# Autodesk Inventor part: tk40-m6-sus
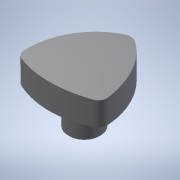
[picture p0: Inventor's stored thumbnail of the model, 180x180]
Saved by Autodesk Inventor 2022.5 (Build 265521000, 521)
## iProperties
Created: 2016-12
Part Number: tk40-m6-sus
Material: 一般
Document SubType Name: Modeling
Designer: imaocorp
Density: 1 g/cm^3
Appearance: 既定
Author: imaocorp
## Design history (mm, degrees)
node "tk40-m6-sus.x_t1"
node "tk40-m6-sus"
node "Base1"
